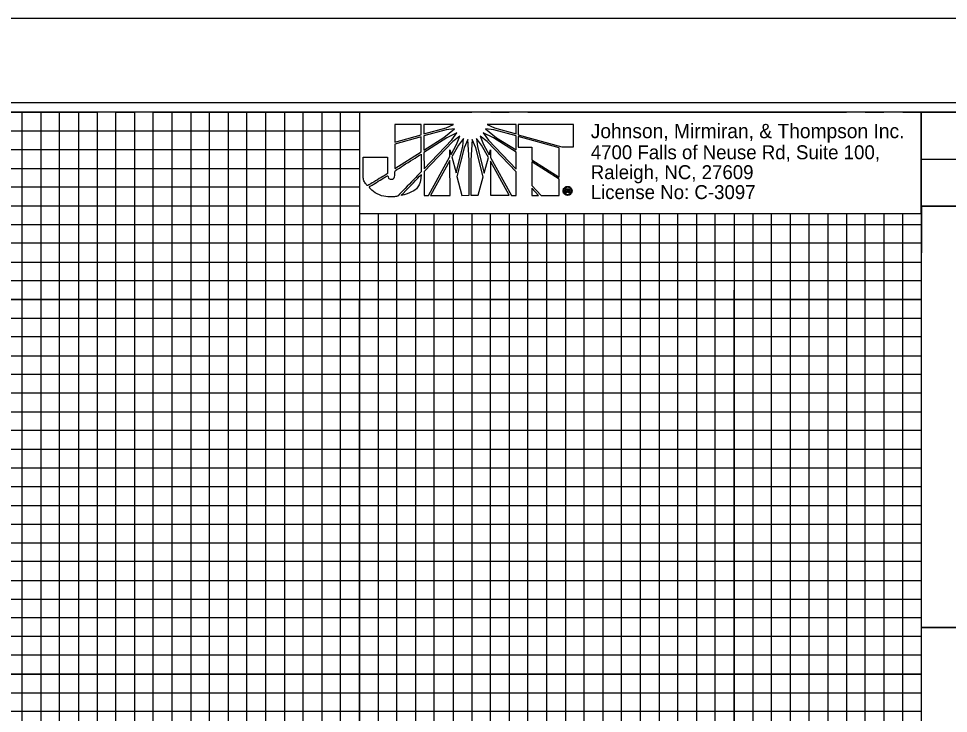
# Model space of a CAD drawing. Extents: x 1648862 to 1650715, y 820691 to 821791.
# Drawn here: x 1650088.3 to 1650336.4, y 821605.5 to 821791 of the extents above; entities that cross this region are included whole.
import ezdxf

# ---------------------------------------------------------------- set-up
doc = ezdxf.new("R2010")
doc.units = 0
for name, color, linetype in [('Prop Dimension Text', 7, 'Continuous'), ('Sheet Cutting Line CELL', 7, 'Continuous'), ('Sheet DOT Grid CELL', 7, 'Continuous'), ('Sheet Plan CELL', 7, 'Continuous'), ('Sheet Plot Border Inside CELL', 7, 'Continuous'), ('Sheet Plot Border Outside CELL', 7, 'Continuous'), ('Sheet Profile CELL', 7, 'Continuous'), ('Sheet Profile Grid Major CELL', 7, 'Continuous'), ('Sheet Profile Grid Middle CELL', 7, 'Continuous'), ('Sheet Profile Grid Minor CELL', 7, 'Continuous'), ('Sheet Sticker Exception Certification CELL', 7, 'Continuous')]:
    doc.layers.add(name, color=color, linetype=linetype)

msp = doc.modelspace()

# ---------------------------------------------------------------- linework, layer by layer
at = {"layer": 'Prop Dimension Text'}
for p, q in [((1650195.74, 821762.71), (1650188.72, 821762.7)), ((1650188.72, 821762.7), (1650188.72, 821758.05)), ((1650195.74, 821760), (1650195.74, 821762.71)), ((1650204.36, 821762.75), (1650196.47, 821762.75)), ((1650196.47, 821762.75), (1650196.47, 821760.23)), ((1650196.47, 821760.23), (1650202.35, 821761.86)), ((1650201.74, 821759.23), (1650204.64, 821761.59)), ((1650202.35, 821761.86), (1650204.36, 821762.75)), ((1650204.64, 821761.59), (1650202.35, 821761.31)), ((1650212.91, 821761.6), (1650215.85, 821759.2)), ((1650215.08, 821761.33), (1650212.91, 821761.6)), ((1650221.09, 821762.73), (1650213.3, 821762.76)), ((1650213.3, 821762.76), (1650215.27, 821761.84)), ((1650215.27, 821761.84), (1650221.09, 821760.21)), ((1650221.09, 821760.21), (1650221.09, 821762.73)), ((1650236.38, 821762.78), (1650221.63, 821762.77)), ((1650221.63, 821762.77), (1650221.63, 821760.06)), ((1650236.39, 821756.74), (1650236.38, 821762.78)), ((1650188.72, 821758.05), (1650195.74, 821760)), ((1650195.74, 821759.49), (1650188.72, 821757.52)), ((1650195.74, 821755.43), (1650195.74, 821759.49)), ((1650202.35, 821761.31), (1650196.47, 821759.69)), ((1650196.47, 821759.69), (1650196.47, 821755.89)), ((1650196.47, 821755.89), (1650201.74, 821759.23)), ((1650202.55, 821759.15), (1650196.47, 821755.28)), ((1650205.22, 821760.51), (1650202.55, 821759.15)), ((1650203.87, 821758.61), (1650205.22, 821760.51)), ((1650206.03, 821759.66), (1650204.17, 821758.22)), ((1650205.18, 821757.42), (1650206.03, 821759.66)), ((1650207.04, 821759.04), (1650205.65, 821757.25)), ((1650206.85, 821756.87), (1650207.04, 821759.04)), ((1650210.48, 821759.04), (1650210.72, 821756.8)), ((1650211.84, 821757.26), (1650210.48, 821759.04)), ((1650211.48, 821759.67), (1650212.34, 821757.42)), ((1650213.34, 821758.23), (1650211.48, 821759.67)), ((1650212.3, 821760.51), (1650213.66, 821758.58)), ((1650215.01, 821759.16), (1650212.3, 821760.51)), ((1650221.05, 821755.33), (1650215.01, 821759.16)), ((1650221.09, 821759.68), (1650215.08, 821761.33)), ((1650215.85, 821759.2), (1650221.05, 821755.96)), ((1650221.05, 821755.96), (1650221.09, 821759.68)), ((1650221.63, 821760.06), (1650221.63, 821759.98)), ((1650221.63, 821759.98), (1650233.25, 821756.74)), ((1650221.63, 821759.56), (1650221.63, 821759.52)), ((1650232.51, 821756.47), (1650221.63, 821759.56)), ((1650221.63, 821759.52), (1650221.64, 821756.69)), ((1650188.72, 821757.52), (1650188.73, 821750.97)), ((1650196.48, 821750.9), (1650203.87, 821758.61)), ((1650204.17, 821758.22), (1650196.48, 821750.16)), ((1650203.71, 821754.74), (1650205.18, 821757.42)), ((1650205.65, 821757.25), (1650203.91, 821754.08)), ((1650205.04, 821749.87), (1650206.85, 821756.87)), ((1650208.2, 821758.73), (1650207.24, 821756.48)), ((1650208.51, 821753.19), (1650208.2, 821758.73)), ((1650209.36, 821758.73), (1650209, 821753.19)), ((1650210.29, 821756.48), (1650209.36, 821758.73)), ((1650210.72, 821756.8), (1650212.54, 821749.71)), ((1650213.66, 821753.97), (1650211.84, 821757.26)), ((1650212.34, 821757.42), (1650213.84, 821754.63)), ((1650221.05, 821750.11), (1650213.34, 821758.23)), ((1650213.66, 821758.58), (1650221.05, 821750.84)), ((1650221.64, 821756.69), (1650225.24, 821756.69)), ((1650225.24, 821756.69), (1650225.24, 821753.32)), ((1650233.25, 821756.74), (1650236.39, 821756.74)), ((1650188.73, 821750.97), (1650195.74, 821755.43)), ((1650196.47, 821755.28), (1650196.48, 821750.9)), ((1650197.64, 821743.79), (1650203.36, 821754.16)), ((1650203.36, 821754.16), (1650203.36, 821756.01)), ((1650203.36, 821756.01), (1650203.71, 821754.74)), ((1650203.91, 821754.08), (1650205.04, 821749.87)), ((1650207.24, 821756.48), (1650205.27, 821748.89)), ((1650212.31, 821748.78), (1650210.29, 821756.48)), ((1650213.84, 821754.63), (1650214.2, 821756.02)), ((1650214.2, 821756.02), (1650214.2, 821753.97)), ((1650221.05, 821750.84), (1650221.05, 821755.33)), ((1650232.52, 821748.72), (1650232.51, 821756.47)), ((1650203.37, 821753.15), (1650198.19, 821743.79)), ((1650203.42, 821743.8), (1650203.37, 821753.15)), ((1650208.52, 821743.84), (1650208.51, 821753.19)), ((1650209, 821753.19), (1650209.01, 821743.84)), ((1650212.54, 821749.71), (1650213.66, 821753.97)), ((1650214.2, 821753.97), (1650219.82, 821743.81)), ((1650219.24, 821743.85), (1650214.2, 821752.97)), ((1650214.2, 821752.97), (1650214.21, 821743.84)), ((1650225.24, 821753.32), (1650232.52, 821748.72)), ((1650225.24, 821752.74), (1650225.25, 821746.47)), ((1650232.52, 821748.18), (1650225.24, 821752.74)), ((1650196.48, 821750.16), (1650196.48, 821743.79)), ((1650221.06, 821743.81), (1650221.05, 821750.11)), ((1650205.27, 821748.89), (1650206.59, 821743.83)), ((1650210.96, 821743.84), (1650212.31, 821748.78)), ((1650232.52, 821743.82), (1650232.52, 821748.18)), ((1650225.25, 821746.47), (1650227.76, 821743.82)), ((1650227.07, 821743.82), (1650225.25, 821745.78)), ((1650225.25, 821745.78), (1650225.25, 821743.82)), ((1650234.37, 821744.49), (1650234.37, 821745.56)), ((1650234.37, 821745.56), (1650234.81, 821745.56)), ((1650234.61, 821744.49), (1650234.37, 821744.49)), ((1650234.81, 821745.36), (1650234.61, 821745.36)), ((1650234.61, 821745.36), (1650234.61, 821745.1)), ((1650234.61, 821745.1), (1650234.81, 821745.1)), ((1650234.81, 821744.91), (1650234.61, 821744.91)), ((1650234.61, 821744.91), (1650234.61, 821744.49)), ((1650234.81, 821746.19), (1650234.81, 821745.97)), ((1650234.81, 821745.97), (1650234.81, 821746.19)), ((1650234.81, 821745.56), (1650234.81, 821745.36)), ((1650234.81, 821745.36), (1650234.81, 821745.56)), ((1650234.81, 821745.56), (1650234.87, 821745.56)), ((1650234.84, 821745.36), (1650234.81, 821745.36)), ((1650234.81, 821745.1), (1650234.81, 821744.91)), ((1650234.81, 821744.91), (1650234.81, 821745.1)), ((1650234.81, 821745.1), (1650234.82, 821745.1)), ((1650234.82, 821744.91), (1650234.81, 821744.91)), ((1650196.48, 821743.79), (1650197.64, 821743.79)), ((1650198.19, 821743.79), (1650203.42, 821743.8)), ((1650206.59, 821743.83), (1650208.52, 821743.84)), ((1650209.01, 821743.84), (1650210.96, 821743.84)), ((1650214.21, 821743.84), (1650219.24, 821743.85)), ((1650219.82, 821743.81), (1650221.06, 821743.81)), ((1650225.25, 821743.82), (1650227.07, 821743.82)), ((1650227.76, 821743.82), (1650232.52, 821743.82)), ((1650234.81, 821744.07), (1650234.81, 821743.83)), ((1650234.81, 821743.83), (1650234.81, 821744.07)), ((1650234.81, 821744.07), (1650234.82, 821744.07)), ((1650234.82, 821743.83), (1650234.81, 821743.83))]:
    msp.add_line(p, q, dxfattribs=at)
msp.add_lwpolyline([(1650179.23, 821738.96), (1650329.18, 821738.96), (1650329.18, 821766.02), (1650179.23, 821766.02)], close=True, dxfattribs=at)
for points in [[(1650188.72, 821758.05), (1650195.74, 821760), (1650195.74, 821762.71), (1650188.72, 821762.7), (1650188.72, 821758.05)], [(1650202.35, 821761.86), (1650204.36, 821762.75), (1650196.47, 821762.75), (1650196.47, 821760.23), (1650202.35, 821761.86)], [(1650196.47, 821759.69), (1650196.47, 821755.89), (1650201.74, 821759.23), (1650204.64, 821761.59), (1650202.35, 821761.31), (1650196.47, 821759.69)], [(1650212.91, 821761.6), (1650215.85, 821759.2), (1650221.05, 821755.96), (1650221.09, 821759.68), (1650215.08, 821761.33), (1650212.91, 821761.6)], [(1650215.27, 821761.84), (1650221.09, 821760.21), (1650221.09, 821762.73), (1650213.3, 821762.76), (1650215.27, 821761.84)], [(1650236.38, 821762.78), (1650221.63, 821762.77), (1650221.63, 821760.06), (1650221.63, 821759.98), (1650233.25, 821756.74), (1650236.39, 821756.74), (1650236.38, 821762.78)], [(1650188.73, 821750.97), (1650195.74, 821755.43), (1650195.74, 821759.49), (1650188.72, 821757.52), (1650188.73, 821750.97)], [(1650196.47, 821755.28), (1650196.48, 821750.9), (1650203.87, 821758.61), (1650205.22, 821760.51), (1650202.55, 821759.15), (1650196.47, 821755.28)], [(1650206.03, 821759.66), (1650204.17, 821758.22), (1650196.48, 821750.16), (1650196.48, 821743.79), (1650197.64, 821743.79), (1650203.36, 821754.16), (1650203.36, 821756.01), (1650203.71, 821754.74), (1650205.18, 821757.42), (1650206.03, 821759.66)], [(1650207.04, 821759.04), (1650205.65, 821757.25), (1650203.91, 821754.08), (1650205.04, 821749.87), (1650206.85, 821756.87), (1650207.04, 821759.04)], [(1650210.48, 821759.04), (1650210.72, 821756.8), (1650212.54, 821749.71), (1650213.66, 821753.97), (1650211.84, 821757.26), (1650210.48, 821759.04)], [(1650211.48, 821759.67), (1650212.34, 821757.42), (1650213.84, 821754.63), (1650214.2, 821756.02), (1650214.2, 821753.97), (1650219.82, 821743.81), (1650221.06, 821743.81), (1650221.05, 821750.11), (1650213.34, 821758.23), (1650211.48, 821759.67)], [(1650212.3, 821760.51), (1650213.66, 821758.58), (1650221.05, 821750.84), (1650221.05, 821755.33), (1650215.01, 821759.16), (1650212.3, 821760.51)], [(1650221.63, 821759.56), (1650221.63, 821759.52), (1650221.64, 821756.69), (1650225.24, 821756.69), (1650225.24, 821753.32), (1650232.52, 821748.72), (1650232.51, 821756.47), (1650221.63, 821759.56)], [(1650207.24, 821756.48), (1650205.27, 821748.89), (1650206.59, 821743.83), (1650208.52, 821743.84), (1650208.51, 821753.19), (1650208.2, 821758.73), (1650207.24, 821756.48)], [(1650209.36, 821758.73), (1650209, 821753.19), (1650209.01, 821743.84), (1650210.96, 821743.84), (1650212.31, 821748.78), (1650210.29, 821756.48), (1650209.36, 821758.73)], [(1650198.19, 821743.79), (1650203.42, 821743.8), (1650203.37, 821753.15), (1650198.19, 821743.79)], [(1650214.21, 821743.84), (1650219.24, 821743.85), (1650214.2, 821752.97), (1650214.21, 821743.84)], [(1650225.24, 821752.74), (1650225.25, 821746.47), (1650227.76, 821743.82), (1650232.52, 821743.82), (1650232.52, 821748.18), (1650225.24, 821752.74), (1650225.24, 821752.74)], [(1650225.25, 821743.82), (1650225.25, 821743.82), (1650227.07, 821743.82), (1650225.25, 821745.78), (1650225.25, 821743.82)], [(1650235.28, 821744.74), (1650235.28, 821744.68), (1650235.28, 821744.64), (1650235.28, 821744.61), (1650235.31, 821744.49), (1650235.09, 821744.49)]]:
    msp.add_lwpolyline(points, dxfattribs=at)
for points, degree in [([(1650187.73, 821748.13), (1650187.31, 821748.13), (1650186.95, 821748.37), (1650186.8, 821749.14), (1650186.8, 821749.14), (1650181.76, 821746.02), (1650181.76, 821746.02), (1650183.32, 821744.39), (1650185.8, 821743.42), (1650187.89, 821743.42), (1650188.44, 821743.42), (1650188.85, 821743.47), (1650189.43, 821743.59), (1650189.43, 821743.59), (1650195.75, 821750.12), (1650195.75, 821750.12), (1650195.75, 821750.12), (1650195.74, 821754.85), (1650195.74, 821754.85), (1650195.74, 821754.85), (1650188.73, 821750.38), (1650188.73, 821750.38), (1650188.73, 821748.61), (1650188.3, 821748.14), (1650187.73, 821748.13)], 3), ([(1650187.73, 821748.13), (1650187.31, 821748.13), (1650186.95, 821748.37), (1650186.8, 821749.14), (1650186.8, 821749.14), (1650181.76, 821746.02), (1650181.76, 821746.02), (1650183.32, 821744.39), (1650185.8, 821743.42), (1650187.89, 821743.42), (1650188.44, 821743.42), (1650188.85, 821743.47), (1650189.43, 821743.59), (1650189.43, 821743.59), (1650195.75, 821750.12), (1650195.75, 821750.12), (1650195.75, 821750.12), (1650195.74, 821754.85), (1650195.74, 821754.85), (1650195.74, 821754.85), (1650188.73, 821750.38), (1650188.73, 821750.38), (1650188.73, 821748.61), (1650188.3, 821748.14), (1650187.73, 821748.13)], 3), ([(1650186.71, 821753.98), (1650186.71, 821753.98), (1650180.22, 821753.98), (1650180.22, 821753.98), (1650180.22, 821753.98), (1650180.22, 821749.91), (1650180.22, 821749.91), (1650180.22, 821749.91), (1650180.22, 821749.48), (1650180.22, 821749.48), (1650180.22, 821748.21), (1650180.64, 821747.2), (1650181.38, 821746.36), (1650181.38, 821746.36), (1650186.72, 821749.6), (1650186.72, 821749.69), (1650186.72, 821749.69), (1650186.71, 821753.98), (1650186.71, 821753.98)], 3), ([(1650195.75, 821749.38), (1650195.75, 821749.38), (1650190.29, 821743.74), (1650190.29, 821743.74), (1650192.96, 821744.4), (1650195.63, 821746.17), (1650195.75, 821749.38)], 3), ([(1650234.81, 821743.83), (1650234.49, 821743.83), (1650234.2, 821743.95), (1650233.97, 821744.18), (1650233.73, 821744.41), (1650233.62, 821744.69), (1650233.62, 821745.02), (1650233.62, 821745.35), (1650233.73, 821745.64), (1650233.97, 821745.85), (1650234.2, 821746.08), (1650234.47, 821746.19), (1650234.81, 821746.19)], 3), ([(1650234.81, 821745.97), (1650234.54, 821745.97), (1650234.32, 821745.88), (1650234.13, 821745.71), (1650233.95, 821745.52), (1650233.85, 821745.29), (1650233.85, 821745.02), (1650233.85, 821744.76), (1650233.95, 821744.53), (1650234.13, 821744.34), (1650234.32, 821744.16), (1650234.54, 821744.07), (1650234.81, 821744.07)], 3), ([(1650234.81, 821746.19), (1650235.14, 821746.19), (1650235.42, 821746.08), (1650235.65, 821745.85), (1650235.89, 821745.64), (1650236.01, 821745.36), (1650236.01, 821745.03)], 3), ([(1650234.82, 821744.07), (1650235.08, 821744.07), (1650235.3, 821744.16), (1650235.49, 821744.34), (1650235.67, 821744.53), (1650235.77, 821744.76), (1650235.77, 821745.03), (1650235.77, 821745.29), (1650235.67, 821745.52), (1650235.49, 821745.71), (1650235.3, 821745.88), (1650235.08, 821745.97), (1650234.81, 821745.97)], 3), ([(1650234.82, 821745.1), (1650234.97, 821745.1), (1650235.05, 821745.15), (1650235.05, 821745.24), (1650235.05, 821745.32), (1650234.98, 821745.36), (1650234.84, 821745.36)], 3), ([(1650236.01, 821745.03), (1650236.01, 821744.69), (1650235.89, 821744.41), (1650235.67, 821744.18), (1650235.43, 821743.95), (1650235.15, 821743.83), (1650234.82, 821743.83)], 3), ([(1650235, 821744.87), (1650234.97, 821744.89), (1650234.91, 821744.91), (1650234.82, 821744.91)], 2), ([(1650234.87, 821745.56), (1650235.15, 821745.56), (1650235.28, 821745.45), (1650235.28, 821745.24), (1650235.28, 821745.14), (1650235.25, 821745.06), (1650235.16, 821745)], 3), ([(1650235.09, 821744.49), (1650235.06, 821744.55), (1650235.04, 821744.61), (1650235.04, 821744.68), (1650235.04, 821744.78), (1650235.03, 821744.84), (1650235, 821744.87)], 3), ([(1650235.16, 821745), (1650235.23, 821744.97), (1650235.27, 821744.88), (1650235.28, 821744.74)], 2)]:
    msp.add_open_spline(points, degree=degree, dxfattribs=at)
at = {"layer": 'Sheet Cutting Line CELL'}
msp.add_line((1650546.28, 821791.02), (1648862.28, 821791.02), dxfattribs=at)
at = {"layer": 'Sheet DOT Grid CELL'}
for p, q in [((1650129.28, 821266.02), (1650129.28, 821718.48)), ((1650229.28, 821266.02), (1650229.28, 821718.48)), ((1650279.28, 821266.02), (1650279.28, 821718.48)), ((1650329.23, 821716.02), (1649029.28, 821716.02)), ((1650179.28, 821266.02), (1650179.28, 821716.02)), ((1650329.23, 821666.02), (1649029.28, 821666.02)), ((1650329.28, 821266.02), (1650329.28, 821628.47)), ((1650329.28, 821616.02), (1649029.28, 821616.02))]:
    msp.add_line(p, q, dxfattribs=at)
at = {"layer": 'Sheet Plan CELL'}
for p, q in [((1650329.18, 821740.94), (1650329.18, 821728.45)), ((1650329.18, 821740.94), (1650329.18, 821728.45)), ((1650329.23, 821740.94), (1650329.23, 821728.45))]:
    msp.add_line(p, q, dxfattribs=at)
at = {"layer": 'Sheet Plot Border Inside CELL'}
msp.add_lwpolyline([(1648875.28, 820713.47), (1650541.78, 820713.47), (1650541.78, 821768.57), (1648875.28, 821768.57)], close=True, dxfattribs=at)
at = {"layer": 'Sheet Plot Border Outside CELL'}
msp.add_lwpolyline([(1648862.28, 820691.02), (1650546.28, 820691.02), (1650546.28, 821791.02), (1648862.28, 821791.02)], close=True, dxfattribs=at)
at = {"layer": 'Sheet Profile CELL'}
msp.add_line((1650329.23, 821753.47), (1650529.28, 821753.47), dxfattribs=at)
for points in [[(1650529.28, 821766.02), (1649029.28, 821766.02), (1649029.28, 820716.02), (1650529.28, 820716.02)], [(1650329.23, 821766.02), (1650529.28, 821766.02), (1650529.28, 821740.97), (1650329.23, 821740.97)], [(1650329.23, 821740.97), (1650429.28, 821740.97), (1650429.28, 821628.47), (1650329.23, 821628.47)]]:
    msp.add_lwpolyline(points, close=True, dxfattribs=at)
at = {"layer": 'Sheet Profile Grid Major CELL'}
for points in [[(1650079.23, 821266.02), (1650129.23, 821266.02), (1650129.23, 821766.02), (1650179.23, 821766.02), (1650179.23, 821266.02), (1650229.23, 821266.02), (1650229.23, 821738.96)], [(1650229.23, 821766.02), (1650279.23, 821766.02)], [(1650279.23, 821738.96), (1650279.23, 821266.02), (1650329.23, 821266.02), (1650329.23, 821766.02), (1650355.53, 821766.02)], [(1649029.23, 821716.02), (1650329.23, 821716.02)], [(1650329.23, 821666.02), (1649029.23, 821666.02), (1649029.23, 821616.02), (1650329.23, 821616.02)]]:
    msp.add_lwpolyline(points, dxfattribs=at)
at = {"layer": 'Sheet Profile Grid Middle CELL'}
msp.add_line((1649029.23, 821741.02), (1650179.23, 821741.02), dxfattribs=at)
for points in [[(1650054.23, 821766.02), (1650104.23, 821766.02), (1650104.23, 821266.02), (1650154.23, 821266.02), (1650154.23, 821766.02), (1650204.23, 821766.02)], [(1650254.23, 821766.02), (1650304.23, 821766.02)], [(1650204.23, 821738.96), (1650204.23, 821266.02), (1650254.23, 821266.02), (1650254.23, 821738.96)], [(1650304.23, 821738.96), (1650304.23, 821266.02), (1650354.23, 821266.02), (1650354.23, 821604.97)], [(1650329.23, 821691.02), (1649029.23, 821691.02), (1649029.23, 821641.02), (1650329.23, 821641.02)]]:
    msp.add_lwpolyline(points, dxfattribs=at)
at = {"layer": 'Sheet Profile Grid Minor CELL'}
for p, q in [((1649079.23, 821761.02), (1650179.23, 821761.02)), ((1650329.18, 821761.02), (1650329.23, 821761.02)), ((1650179.23, 821755.98), (1649079.23, 821755.67)), ((1650329.23, 821756.02), (1650329.18, 821756.02)), ((1649079.23, 821751.02), (1650179.23, 821751.02)), ((1650329.18, 821751.02), (1650329.23, 821751.02)), ((1650329.18, 821631.02), (1649079.23, 821631.02)), ((1650329.23, 821626.02), (1649079.23, 821626.02)), ((1650329.23, 821621.02), (1649079.23, 821621.02)), ((1649079.23, 821611.02), (1650329.23, 821611.02)), ((1650329.23, 821606.02), (1649079.23, 821606.02))]:
    msp.add_line(p, q, dxfattribs=at)
for points in [[(1650089.23, 821266.02), (1650089.23, 821766.02), (1650094.23, 821766.02), (1650094.23, 821266.02)], [(1650099.23, 821266.02), (1650099.23, 821766.02), (1650109.23, 821766.02), (1650109.23, 821266.02)], [(1650114.23, 821266.02), (1650114.23, 821766.02), (1650119.23, 821766.02), (1650119.23, 821266.02)], [(1650124.23, 821266.02), (1650124.23, 821766.02), (1650134.23, 821766.02), (1650134.23, 821266.02)], [(1650139.23, 821266.02), (1650139.23, 821766.02), (1650144.23, 821766.02), (1650144.23, 821266.02)], [(1650149.23, 821266.02), (1650149.23, 821766.02), (1650159.23, 821766.02), (1650159.23, 821266.02)], [(1650164.23, 821266.02), (1650164.23, 821766.02), (1650169.23, 821766.02), (1650169.23, 821266.02)], [(1650174.23, 821266.02), (1650174.23, 821766.02), (1650184.23, 821766.02)], [(1650189.23, 821766.02), (1650194.23, 821766.02)], [(1650199.23, 821766.02), (1650209.23, 821766.02)], [(1650214.23, 821766.02), (1650219.23, 821766.02)], [(1650224.23, 821766.02), (1650234.23, 821766.02)], [(1650239.23, 821766.02), (1650244.23, 821766.02)], [(1650249.23, 821766.02), (1650259.23, 821766.02)], [(1650264.23, 821766.02), (1650269.23, 821766.02)], [(1650274.23, 821766.02), (1650284.23, 821766.02)], [(1650289.23, 821766.02), (1650294.23, 821766.02)], [(1650299.23, 821766.02), (1650309.23, 821766.02)], [(1650314.23, 821766.02), (1650319.23, 821766.02)], [(1650324.23, 821766.02), (1650334.23, 821766.02)], [(1650179.23, 821746.02), (1649079.23, 821746.02), (1649079.23, 821736.02), (1650329.23, 821736.02)], [(1650329.23, 821746.02), (1650329.18, 821746.02)], [(1650184.23, 821738.96), (1650184.23, 821266.02), (1650189.23, 821266.02), (1650189.23, 821738.96)], [(1650194.23, 821738.96), (1650194.23, 821266.02), (1650199.23, 821266.02), (1650199.23, 821738.96)], [(1650209.23, 821738.96), (1650209.23, 821266.02), (1650214.23, 821266.02), (1650214.23, 821738.96)], [(1650219.23, 821266.02), (1650224.23, 821266.02), (1650224.23, 821738.96)], [(1650219.23, 821738.96), (1650219.23, 821266.02)], [(1650234.23, 821738.96), (1650234.23, 821266.02), (1650239.23, 821266.02), (1650239.23, 821738.96)], [(1650244.23, 821738.96), (1650244.23, 821266.02), (1650249.23, 821266.02), (1650249.23, 821738.96)], [(1650259.23, 821738.96), (1650259.23, 821266.02), (1650264.23, 821266.02), (1650264.23, 821738.96)], [(1650269.23, 821738.96), (1650269.23, 821266.02), (1650274.23, 821266.02), (1650274.23, 821738.96)], [(1650284.23, 821738.96), (1650284.23, 821266.02), (1650289.23, 821266.02), (1650289.23, 821738.96)], [(1650294.23, 821738.96), (1650294.23, 821266.02), (1650299.23, 821266.02), (1650299.23, 821738.96)], [(1650309.23, 821738.96), (1650309.23, 821266.02), (1650314.23, 821266.02), (1650314.23, 821738.96)], [(1650319.23, 821738.96), (1650319.23, 821266.02), (1650324.23, 821266.02), (1650324.23, 821738.96)], [(1650329.18, 821731.02), (1649079.23, 821731.02), (1649079.23, 821726.02), (1650329.23, 821726.02)], [(1650329.23, 821721.02), (1649079.23, 821721.02), (1649079.23, 821711.02), (1650329.23, 821711.02)], [(1650329.23, 821706.02), (1649079.23, 821706.02), (1649079.23, 821701.02), (1650329.23, 821701.02)], [(1650329.23, 821696.02), (1649079.23, 821696.02), (1649079.23, 821686.02), (1650329.23, 821686.02)], [(1650329.23, 821681.02), (1649079.23, 821681.02), (1649079.23, 821676.02), (1650329.23, 821676.02)], [(1650329.23, 821671.02), (1649079.23, 821671.02), (1649079.23, 821661.02), (1650329.23, 821661.02)], [(1650329.23, 821655.92), (1649079.33, 821655.92), (1649079.33, 821651.02), (1650329.23, 821651.02)], [(1650329.23, 821646.02), (1649079.23, 821646.02), (1649079.23, 821636.02), (1650329.23, 821636.02)]]:
    msp.add_lwpolyline(points, dxfattribs=at)
at = {"layer": 'Sheet Sticker Exception Certification CELL'}
for p, q in [((1650329.23, 821604.97), (1650329.23, 821628.47)), ((1650329.23, 821628.47), (1650529.27, 821628.47)), ((1650329.23, 821604.97), (1650329.23, 821628.47)), ((1650329.23, 821628.47), (1650529.27, 821628.47))]:
    msp.add_line(p, q, dxfattribs=at)

# ---------------------------------------------------------------- texts
at = {"layer": 'Prop Dimension Text'}
for s, height, p in [('Johnson, Mirmiran, & Thompson Inc.', 3.8315, (1650240.98, 821759.09)), ('4700 Falls of Neuse Rd, Suite 100, ', 3.722, (1650240.98, 821753.47)), ('Raleigh, NC, 27609', 3.722, (1650240.98, 821748.15)), ('License No: C-3097', 3.722, (1650240.98, 821742.83))]:
    msp.add_text(s, height=height, rotation=360, dxfattribs=at).set_placement(p)

doc.saveas('drawing.dxf')
